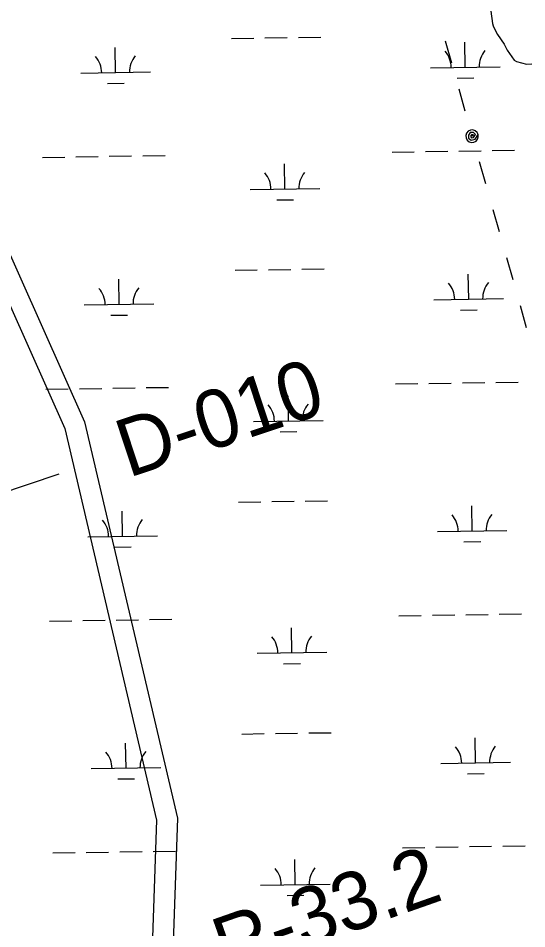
# Model space of a CAD drawing. Extents: x 3807117 to 3845308, y 337856 to 363736.
# Drawn here: x 3834037 to 3834768, y 347636 to 348942 of the extents above; entities that cross this region are included whole.
import ezdxf

# ---------------------------------------------------------------- set-up
doc = ezdxf.new("R2010")
doc.units = 0
for name, color, linetype in [('V-RIVR-RANG', 7, 'Continuous'), ('V-RIVR-RANG-IDEN', 7, 'Continuous'), ('V-ROAD-CNTR', 7, 'Continuous'), ('V-SITE-VEGE', 7, 'Continuous'), ('V-UTIL-LINE', 7, 'Continuous'), ('V-WETL-SWMP', 7, 'Continuous')]:
    doc.layers.add(name, color=color, linetype=linetype)

msp = doc.modelspace()

# ---------------------------------------------------------------- linework, layer by layer
at = {"layer": 'V-RIVR-RANG'}
msp.add_line((3834095.8, 348287.9), (3833090.1, 347953), dxfattribs=at)
at = {"layer": 'V-ROAD-CNTR'}
for points in [[(3831835, 350986.7), (3832411.1, 350479.1), (3832910.4, 350016.2), (3833595.4, 349381.1), (3833766.7, 349184.4), (3834132.8, 348363.2), (3834266, 347794.4), (3834253.3, 347423.7), (3834191.2, 347105.4), (3834089.5, 346764.4), (3834056.4, 346524.5), (3834053.8, 346408.9), (3834082.2, 346293.7), (3834179.5, 346287), (3834268.9, 346281.8), (3834321.2, 346229.5), (3834326.5, 346154.9)], [(3831816.7, 350962.9), (3832391, 350456.8), (3832890, 349994.2), (3833573.8, 349360.2), (3833741.1, 349168.1), (3834104.2, 348353.6), (3834235.9, 347791.5), (3834223.4, 347427.1), (3834162.1, 347112.5), (3834060.1, 346770.7), (3834026.5, 346526.9), (3834023.7, 346405.6), (3834058.3, 346265.2), (3834177.6, 346257.1), (3834255.7, 346252.5), (3834292.1, 346216.2), (3834296.6, 346152.8)]]:
    msp.add_lwpolyline(points, dxfattribs=at)
at = {"layer": 'V-SITE-VEGE'}
for points in [[(3834716, 348952.1), (3834718.3, 348934.6), (3834719.3, 348931.4), (3834722.5, 348924), (3834725.7, 348918.9), (3834735, 348905.1), (3834739.6, 348896.4), (3834749.3, 348882.1)], [(3834749.3, 348882.1), (3834753, 348879.8), (3834767.3, 348876.1), (3834774.6, 348876.6)]]:
    msp.add_lwpolyline(points, dxfattribs=at)
at = {"layer": 'V-UTIL-LINE'}
for points in [[(3834650.3, 348909.5), (3834659.3, 348877.9)], [(3834669.8, 348840.7), (3834678.8, 348809.1)], [(3834689.1, 348772.8), (3834690.9, 348775), (3834688.6, 348775.2), (3834686.9, 348773.1), (3834688, 348770.4), (3834691.3, 348771.1), (3834693.7, 348775.2), (3834690.9, 348778.4), (3834686.1, 348778.4), (3834683.7, 348774.5), (3834683.9, 348770), (3834687.9, 348767.3), (3834693.3, 348768.5), (3834697.8, 348775.3), (3834696.2, 348778.4), (3834693.5, 348780.7), (3834690.1, 348781.8), (3834686.6, 348781.5), (3834683.5, 348779.9), (3834681.2, 348777.2), (3834680.2, 348773.9), (3834680.4, 348770.4), (3834682, 348767.2), (3834684.7, 348765), (3834688.1, 348763.9), (3834691.6, 348764.2), (3834694.7, 348765.8), (3834697, 348768.4), (3834698, 348771.8), (3834697.8, 348775.3)], [(3834699.4, 348736.6), (3834708.4, 348705)], [(3834718.9, 348667.8), (3834727.9, 348636.2)], [(3834738.4, 348599), (3834747.4, 348567.4)], [(3834757.9, 348530.2), (3834766.9, 348498.6)]]:
    msp.add_lwpolyline(points, dxfattribs=at)
at = {"layer": 'V-WETL-SWMP'}
for p, q in [((3834343.7, 348913.1), (3834375.7, 348913.6)), ((3834391.7, 348913.8), (3834423.7, 348914.3)), ((3834439.7, 348914.6), (3834471.7, 348915)), ((3834177.3, 348864.2), (3834176.8, 348900.2)), ((3834679.2, 348871.7), (3834678.6, 348907.7)), ((3834629.2, 348871), (3834729.2, 348872.5)), ((3834127.3, 348863.5), (3834227.3, 348865)), ((3834667.4, 348856.1), (3834691.4, 348856.5)), ((3834165.6, 348848.6), (3834189.6, 348849)), ((3834670.1, 348751.5), (3834702.1, 348752)), ((3834718.1, 348752.2), (3834750.1, 348752.7)), ((3834072.3, 348742.5), (3834104.3, 348743)), ((3834120.3, 348743.3), (3834152.3, 348743.7)), ((3834168.3, 348744), (3834200.3, 348744.5)), ((3834216.3, 348744.7), (3834248.3, 348745.2)), ((3834574.1, 348750.1), (3834606.1, 348750.5)), ((3834622.1, 348750.8), (3834654.1, 348751.3)), ((3834420.3, 348697), (3834419.8, 348733)), ((3834370.3, 348696.3), (3834470.3, 348697.8)), ((3834408.6, 348681.4), (3834432.6, 348681.8)), ((3834444.7, 348581.9), (3834476.6, 348582.4)), ((3834348.7, 348580.5), (3834380.7, 348581)), ((3834396.7, 348581.2), (3834428.7, 348581.7)), ((3834684.2, 348539.1), (3834683.6, 348575.1)), ((3834182.3, 348531.6), (3834181.8, 348567.6)), ((3834132.3, 348530.8), (3834232.3, 348532.3)), ((3834634.2, 348538.3), (3834734.2, 348539.8)), ((3834672.4, 348523.5), (3834696.4, 348523.8)), ((3834170.5, 348516), (3834194.5, 348516.3)), ((3834221.3, 348412.1), (3834253.3, 348412.5)), ((3834579.1, 348417.4), (3834611.1, 348417.9)), ((3834627.1, 348418.1), (3834659.1, 348418.6)), ((3834675.1, 348418.9), (3834707.1, 348419.3)), ((3834723.1, 348419.6), (3834755.1, 348420.1)), ((3834077.3, 348409.9), (3834109.3, 348410.4)), ((3834125.3, 348410.6), (3834157.3, 348411.1)), ((3834173.3, 348411.3), (3834205.3, 348411.8)), ((3834425.3, 348364.4), (3834424.8, 348400.4)), ((3834375.3, 348363.6), (3834475.3, 348365.1)), ((3834413.6, 348348.8), (3834437.5, 348349.1)), ((3834353.6, 348247.9), (3834385.6, 348248.3)), ((3834401.6, 348248.6), (3834433.6, 348249.1)), ((3834449.6, 348249.3), (3834481.6, 348249.8)), ((3834689.1, 348206.4), (3834688.6, 348242.4)), ((3834187.3, 348198.9), (3834186.8, 348234.9)), ((3834639.2, 348205.7), (3834739.1, 348207.2)), ((3834137.3, 348198.2), (3834237.3, 348199.7)), ((3834677.4, 348190.8), (3834701.4, 348191.2)), ((3834175.5, 348183.3), (3834199.5, 348183.7)), ((3834632.1, 348085.5), (3834664.1, 348086)), ((3834680.1, 348086.2), (3834712.1, 348086.7)), ((3834728.1, 348086.9), (3834760.1, 348087.4)), ((3834082.3, 348077.3), (3834114.3, 348077.7)), ((3834130.3, 348078), (3834162.3, 348078.5)), ((3834178.3, 348078.7), (3834210.3, 348079.2)), ((3834226.2, 348079.4), (3834258.2, 348079.9)), ((3834584.1, 348084.8), (3834616.1, 348085.3)), ((3834430.3, 348031.7), (3834429.8, 348067.7)), ((3834380.3, 348031), (3834480.3, 348032.5)), ((3834418.5, 348016.1), (3834442.5, 348016.5)), ((3834358.6, 347915.2), (3834390.6, 347915.7)), ((3834406.6, 347915.9), (3834438.6, 347916.4)), ((3834454.6, 347916.7), (3834486.6, 347917.1)), ((3834694.1, 347873.8), (3834693.6, 347909.8)), ((3834192.3, 347866.3), (3834191.7, 347902.3)), ((3834142.3, 347865.5), (3834242.3, 347867)), ((3834644.1, 347873.1), (3834744.1, 347874.6)), ((3834180.5, 347850.7), (3834204.5, 347851)), ((3834682.4, 347858.2), (3834706.4, 347858.6)), ((3834135.2, 347745.4), (3834167.2, 347745.8)), ((3834183.2, 347746.1), (3834215.2, 347746.5)), ((3834231.2, 347746.8), (3834263.2, 347747.3)), ((3834589.1, 347752.1), (3834621.1, 347752.6)), ((3834637.1, 347752.9), (3834669.1, 347753.3)), ((3834685.1, 347753.6), (3834717.1, 347754.1)), ((3834733.1, 347754.3), (3834765.1, 347754.8)), ((3834087.2, 347744.6), (3834119.2, 347745.1)), ((3834435.3, 347699.1), (3834434.7, 347735.1)), ((3834385.3, 347698.3), (3834485.3, 347699.8)), ((3834423.5, 347683.5), (3834447.5, 347683.8))]:
    msp.add_line(p, q, dxfattribs=at)
for centre, start, end in [((3834734.4, 348873), 140.0865, 181.6302), ((3834122.1, 348863.8), 0.0865, 41.6302), ((3834232.6, 348865.5), 140.0865, 181.6302), ((3834623.9, 348871.4), 0.0865, 41.6302), ((3834365.1, 348696.7), 0.0865, 41.6302), ((3834475.6, 348698.3), 140.0865, 181.6302), ((3834628.9, 348538.7), 0.0865, 41.6302), ((3834739.4, 348540.4), 140.0865, 181.6302), ((3834127.1, 348531.2), 0.0865, 41.6302), ((3834237.5, 348532.9), 140.0865, 181.6302), ((3834370.1, 348364), 0.0865, 41.6302), ((3834480.5, 348365.7), 140.0865, 181.6302), ((3834633.9, 348206.1), 0.0865, 41.6302), ((3834744.4, 348207.7), 140.0865, 181.6302), ((3834132.1, 348198.6), 0.0865, 41.6302), ((3834242.5, 348200.2), 140.0865, 181.6302), ((3834375.1, 348031.4), 0.0865, 41.6302), ((3834485.5, 348033), 140.0865, 181.6302), ((3834247.5, 347867.6), 140.0865, 181.6302), ((3834638.9, 347873.5), 0.0865, 41.6302), ((3834749.4, 347875.1), 140.0865, 181.6302), ((3834137, 347865.9), 0.0865, 41.6302), ((3834380, 347698.7), 0.0865, 41.6302), ((3834490.5, 347700.4), 140.0865, 181.6302)]:
    msp.add_arc(centre, 35.2, start, end, dxfattribs=at)

# ---------------------------------------------------------------- texts
at = {"layer": 'V-RIVR-RANG-IDEN'}
for s, rotation, p in [('D-010', 18.2773, (3834195.5, 348282.5)), ('R-33.2', 19.3772, (3834335.9, 347567.7))]:
    msp.add_text(s, height=83, rotation=rotation, dxfattribs=at).set_placement(p)

doc.saveas('drawing.dxf')
